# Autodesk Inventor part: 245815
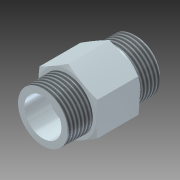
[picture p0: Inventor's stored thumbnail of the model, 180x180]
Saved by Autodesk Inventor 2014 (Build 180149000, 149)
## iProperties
Shininess: 20.0
Length Units: 11272
Angle Units: 11279
Time Units: 11290
Mass Units: 11286
Length Display Precision: 3
Angle Display Precision: 2
Company: Autodesk, Inc.
Created: 2001-12
Part Number: 245815
Material: Stainless Steel 316
Description: FITTING; ST-B12-C910-(SS)
Document SubType Name: Modeling
Designer: Autodesk, Inc.
Density: 8.182 g/cm^3
Appearance: Stainless Steel
Density: 7.86
Volumn: 5.818506058552819
Area: 35.84085697721723
PropertySet Name: Model Information
Control State: 0
Master: False
Checked Out: False
Last Check In By: JT
Last Check In Date: 2003-06-20
MODEL - 1: ---
MODEL - 2: ---
RAW MATERIAL: --------
SCALE:: 1=??
SIZE: 00 x 00 x 00
SUB-ASSY - 1: ------
SUB-ASSY - 1 - QUA: 1
SUB-ASSY - 2: ------
SUB-ASSY - 2 - QUA: 1
SYM. TO:: N/A
TEMPLATE CREATION: -- / __-__-__
Title: FITTING; ST-B12-C910-(SS)
Author: Autodesk, Inc.
Comments: ORING = -016
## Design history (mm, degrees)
sketch "Sketch1"
  geometry: L1 (0, 16.498)-(14.288, 8.249); L2 (14.288, 8.249)-(14.287, -8.249); L3 (14.287, -8.249)-(0, -16.498); L4 (0, -16.498)-(-14.287, -8.249); L5 (-14.287, -8.249)-(-14.287, 8.249); L6 (-14.287, 8.249)-(0, 16.498); C1 r 6.096 at (0, 0); 2 further points
  constraints: 12 end point, 2 coincident, 1 centre point, 1 vertical alignment, 11 other
  dimensions: "d3" = 28.575 distance between parallel lines of L4 L1 (= Hex_Size); "d42" = 12.192 diameter of C1 (= Face_Seal_ID)
extrude "Hex Nut Extrusion" new body sketch "Sketch1" distance "d4" = 21.4376 (= L5 - BB - CC); taper "d5" = 0 deg
sketch "Sketch2"
  geometry: L1 (4.912, 0)-(23.813, 0); L2 (4.825, 21.438)-(14.86, 21.438); L3 (14.287, 21.438)-(14.287, 0); L4 (0, 0)-(0, 27.779); L5 (14.287, 0)-(23.813, 2.552); L6 (14.287, 21.438)-(23.812, 18.885); L7 (14.287, 0)-(10.745, 0); L8 (23.812, 21.438)-(14.287, 21.438); L9 (23.813, 0)-(23.813, 2.552); L10 (23.812, 18.885)-(23.812, 21.438); L11 (14.287, 0)-(23.813, 0)
  constraints: 22 end point, 6 perpendicular, 5 point on line, 2 parallel, 1 collinear, 1 horizontal
  dimensions: "d6" = 21.4376 distance between parallel lines of L2 L1 (= L5 - BB - CC); "d7" = 28.575 diameter of L3 L4 (= Hex_Size); "d8" = 15 deg angle of L1 L5; "d9" = 15 deg angle of L2 L6; "d10" = 9.525 distance between parallel lines of L10 L3
revolve "Hex Nut Chamfer" sketch "Sketch2" stored, may be unused: angle "d11" = 90 deg
sketch "Sketch3"
  geometry: L1 (0, -22.907)-(0, 22.907); L2 (0, 0)-(12.373, 0) reference; L3 (-12.373, 0)-(0, 0) reference; L4 (-14.287, 0)-(-12.373, 0) reference; L5 (12.373, 0)-(14.287, 0) reference; L6 (12.29, 33.426)-(9.131, 33.426); L7 (9.131, 33.426)-(9.131, 21.438); L8 (9.131, 21.438)-(4.648, 21.438); L9 (11.43, 0)-(11.43, -0.762); L10 (11.43, -0.762)-(12.7, -2.032); L11 (12.7, -2.032)-(12.7, -11.532); L12 (12.7, -11.532)-(11.43, -12.802); L13 (11.43, -12.802)-(9.5, -12.802); L14 (9.5, -12.802)-(9.5, -11.455); L15 (9.5, -11.455)-(7.341, -11.455); L16 (7.341, -11.455)-(7.341, -12.802); L17 (7.341, -12.802)-(6.096, -12.802); L18 (6.096, -12.802)-(6.096, 0); L19 (6.096, 0)-(11.43, 0); L20 (12.597, 21.438)-(9.131, 21.438); L21 (12.597, 21.438)-(12.29, 33.426); 1 further point
  constraints: 34 end point, 10 perpendicular, 2 collinear, 2 parallel, 2 point on line, 1 coincident, 1 midpoint, 1 vertical
  dimensions: "d12" = 0.762 distance of L9.start L9.end (= Face_Seal_Undercut_Length_H); "d13" = 12.8016 distance between parallel lines of L13 L19 (= CC); "d14" = 45 deg angle of L19 L10; "d15" = 22.86 diameter of L12.end L1 (= Face_Seal_Lip); "d16" = 25.4 diameter of L11 L1 (= Face_Seal_Thread_OD); "d18" = 12.192 diameter of L18 L1 (= Face_Seal_ID); "d19" = 18.9992 diameter of L14 L1 (= Face_Seal_Groove_Dia); "d20" = 2.159 distance between parallel lines of L16 L14; "d21" = 1.3462 distance between parallel lines of L15 L17; "d25" = 24.57907 diameter of L6.start L1 (= Pipe_Lip); "d26" = 18.2626 diameter of L7 L1 (= Pipe_ID); "d43" = 11.9888 distance between parallel lines of L8 L6 (= BB); "d44" = 1.47 deg angle of L7 L21; "d45" = 21.4376 distance between parallel lines of L8 L2 (= d4)
revolve "Oring Face_Seal Revolution" sketch "Sketch3" stored, may be unused: angle "d28" = 90 deg
thread "Faceseal_Thread" dims "d29" = 25.4, "d30" = 0
sketch "Sketch4"
  geometry: L1 (0, -12.403)-(0, 13.958); C1 r 0.787 at (8.712, -12.243); 2 further points
  constraints: 2 end point, 1 centre point, 1 coincident, 1 point on line, 1 vertical
  dimensions: "d33" = 1.5748 diameter of C1 (= Face_Seal_Seal); "d37" = 17.4244 diameter of C1.centre L1 (= Face_Seal_Groove_Dia - Face_Seal_Seal); "d38" = 12.2428 vertical distance of C1.centre point (0, 0) (computed from CC, Face_Seal_Seal)
revolve "Orings" sketch "Sketch4" stored, may be unused: angle "d39" = 90 deg
thread "Thread3" dims "d46" = 25.4, "d47" = 0
body "Solid1"
other parameters: "Hex_Size" = 28.575 [user parameter; used in 2 equation terms], "L5" = 46.228 [user parameter; used in 2 equation terms], "CC" = 12.8016 [user parameter; used in 4 equation terms], "BB" = 11.9888 [user parameter; used in 3 equation terms], "Face_Seal_Undercut_Length_H" = 0.762 [user parameter; used in 1 equation term], "Face_Seal_Thread_OD" = 25.4 [user parameter; used in 1 equation term], "Face_Seal_Lip" = 22.86 [user parameter; used in 1 equation term], "Face_Seal_ID" = 12.192 [user parameter; used in 2 equation terms], "Face_Seal_Groove_Dia" = 18.9992 [user parameter; used in 2 equation terms], "Pipe_Lip" = 24.57907 [user parameter; used in 1 equation term], "Pipe_ID" = 18.2626 [user parameter; used in 1 equation term], "Face_Seal_Seal" = 1.5748 [user parameter; used in 3 equation terms], "HH" = 34.036 [user parameter]
